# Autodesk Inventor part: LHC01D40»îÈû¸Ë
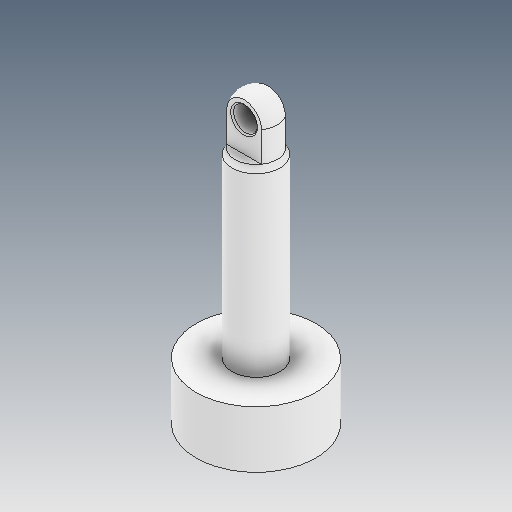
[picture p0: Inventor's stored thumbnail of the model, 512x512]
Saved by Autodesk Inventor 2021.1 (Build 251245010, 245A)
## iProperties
Created: 2021-06
Part Number: LHC01D40»îÈû¸Ë
Material: Ogólny
Document SubType Name: Modeling
Designer: user
Density: 1 g/cm^3
Appearance: Domyślna
Author: user
Revision Number: ÈÎºÎ
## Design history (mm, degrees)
feature "ÊäÈë1"
node "Bryła1"
